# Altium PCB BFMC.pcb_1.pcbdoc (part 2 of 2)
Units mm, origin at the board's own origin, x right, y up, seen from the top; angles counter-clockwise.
Board outline 115.66 x 88.65 mm, 2 copper layers (Top Layer, Bottom Layer); 106 components, 51 nets, 277 pads, 103 vias.
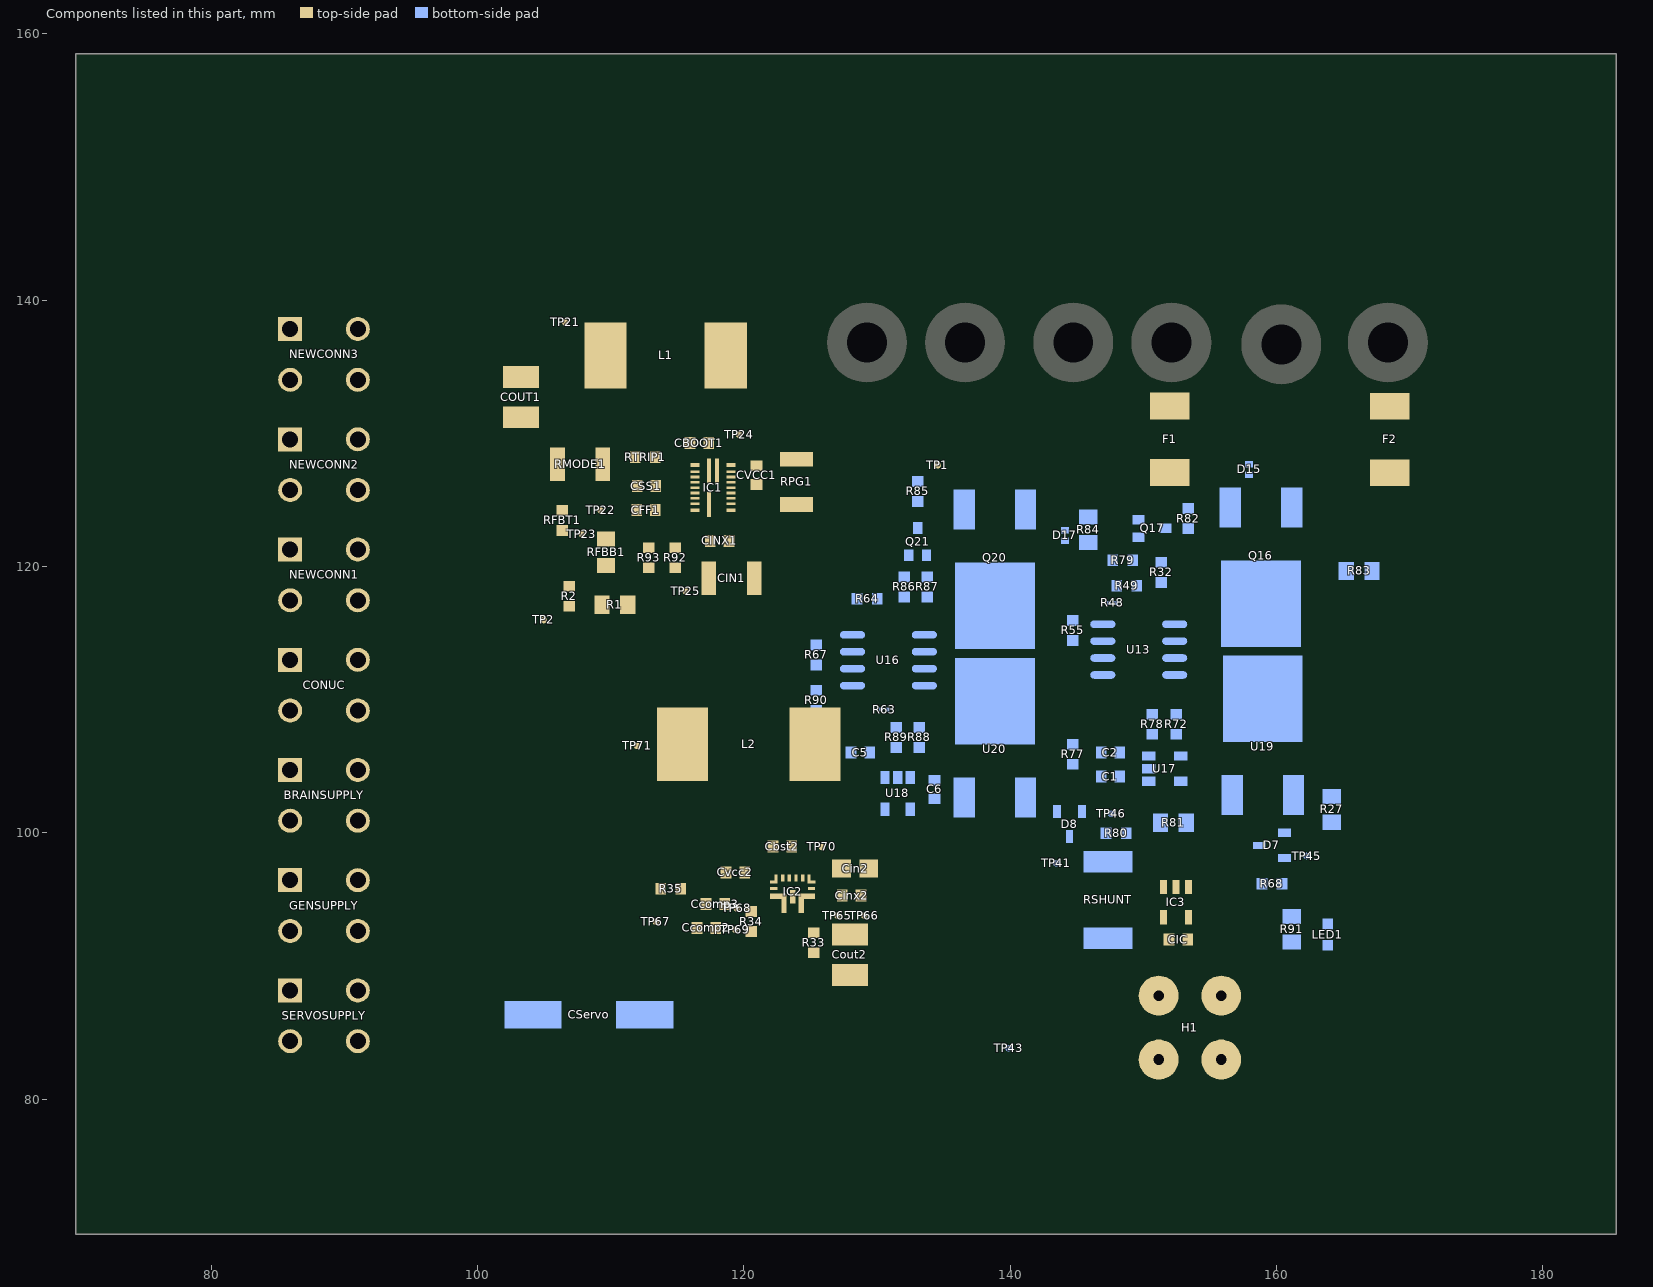
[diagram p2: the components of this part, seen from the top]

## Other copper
Top Layer:
  region net ISHUNT: 154.278,95.663 154.278,96.163 cw(c154.278,99.622) 153.676,96.216 153.676,95.61 cw(c154.278,92.204)
  region net UBATT: 150.494,96.19 150.494,95.69 cw(c150.494,90.33) 151.244,95.637 151.244,96.243 cw(c150.494,101.55)
  region net OUT_BATT: 150.494,93.91 150.494,93.41 cw(c150.494,92.265) 151.244,93.13 151.244,94.2 cw(c150.494,95.025)
  region net +5V: 153.16,92.38 153.66,92.38 ccw(c150.891,92.38) 153.556,93.13 153.263,93.13 ccw(c155.929,92.38)
  region net ADC1: 107.781,116.853 107.781,117.153 cw(c107.781,117.715) 107.331,117.378 107.331,116.628 cw(c107.781,116.29)
  region net ADC1: 106.017,117.153 106.017,116.853 cw(c106.017,116.29) 106.467,116.628 106.467,117.378 cw(c106.017,117.715)
  region net ADC1: 105.326,116.121 105.114,116.333 105.063,116.283 105.046,116.269 105.028,116.257 105.009,116.247 104.987,116.24 104.964,116.236 105.229,115.971 105.232,115.995 105.239,116.016 105.249,116.035 105.262,116.053 105.276,116.071
  region net VOUT1: 124.171,93.762 124.471,93.762 cw(c125.034,93.762) 124.521,93.994 124.121,93.994 cw(c123.607,93.762)
  region: 122.894,93.613 123.148,93.613 cw(c125.87,93.613) 123.174,93.994 122.867,93.994 cw(c120.171,93.613)
  region net VOUT1: 125.737,95.117 125.737,95.371 cw(c125.737,97.884) 125.371,95.398 125.371,95.09 cw(c125.737,92.604)
  region net SW_1: 123.821,95.944 123.521,95.944 cw(c122.517,95.944) 123.489,95.694 123.852,95.694 cw(c124.824,95.944)
  region: 123.17,95.825 122.916,95.825 cw(c122.44,95.825) 122.726,95.444 123.197,95.444 cw(c125.893,95.825)
  region: 121.874,95.371 121.874,95.117 cw(c121.874,94.93) 121.971,95.09 121.971,95.398 cw(c121.874,95.557)
  region net COMP: 119.611,93.991 119.823,94.203 119.792,94.236 119.778,94.253 119.765,94.27 119.753,94.289 119.744,94.308 119.738,94.329 119.735,94.35 119.47,94.085 119.493,94.082 119.513,94.075 119.531,94.066 119.548,94.054 119.563,94.04
  region net COMP: 119.348,94.679 119.136,94.466 119.188,94.417 119.202,94.4 119.215,94.383 119.225,94.364 119.232,94.343 119.236,94.319 119.501,94.584 119.478,94.588 119.457,94.594 119.437,94.604 119.418,94.616 119.399,94.63 119.365,94.662
  region net $3N2936: 119.023,93.01 119.023,92.71 119.047,92.704 119.07,92.69 119.094,92.669 119.116,92.643 119.18,92.564 119.198,92.545 119.198,92.92 119.179,92.911 119.159,92.915 119.138,92.928 119.095,92.969 119.072,92.989 119.048,93.004
  region net $3N2936: 119.704,92.44 119.704,92.74 119.691,92.742 119.679,92.746 119.667,92.753 119.655,92.762 119.643,92.773 119.632,92.785 119.61,92.813 119.558,92.887 119.548,92.9 119.539,92.911 119.529,92.92 119.529,92.545 119.549,92.555 119.569,92.549 119.589,92.533 119.631,92.486 119.653,92.464 119.678,92.447
  region net BOOT: 115.735,127.778 115.735,127.478 ccw(c115.735,128.028) 115.989,127.54 115.989,127.716 ccw(c115.735,127.227)
  region: 115.689,127.228 115.689,127.028 cw(c115.688,-126.865) 115.989,127.028 115.989,127.228 ccw(c115.688,-126.665)
  region net TRIP: 115.689,126.828 115.689,126.628 cw(c115.688,-127.265) 115.989,126.628 115.989,126.828 ccw(c115.688,-127.065)
  region net MODE: 115.689,126.428 115.689,126.228 cw(c115.688,-127.665) 115.989,126.228 115.989,126.428 ccw(c115.688,-127.465)
  region: 115.689,125.628 115.689,125.428 ccw(c115.689,126.535) 115.989,125.469 115.989,125.586 ccw(c115.689,124.52)
  region net EN: 115.689,124.828 115.689,124.628 cw(c115.688,-129.265) 115.989,124.628 115.989,124.828 ccw(c115.688,-129.065)
  region net PGOOD: 115.911,124.378 115.911,124.078 ccw(c115.911,124.158) 115.989,124.14 115.989,124.316 ccw(c115.911,124.298)
  region net VCC: 119.839,127.478 119.839,127.778 ccw(c119.839,126.117) 119.389,127.716 119.389,127.54 ccw(c119.839,129.139)
  region: 118.889,126.728 119.189,126.728 cw(c120.627,126.728) 119.22,127.028 118.857,127.028 cw(c117.45,126.728)
  region: 118.889,126.328 119.189,126.328 cw(c120.627,126.328) 119.22,126.628 118.857,126.628 cw(c117.45,126.328)
  region: 119.189,127.128 118.889,127.128 cw(c118.564,127.128) 118.689,126.828 119.389,126.828 cw(c119.514,127.128)
  region: 118.889,125.928 119.189,125.928 cw(c120.627,125.928) 119.22,126.228 118.857,126.228 cw(c117.45,125.928)
  region: 119.189,126.728 118.889,126.728 cw(c118.564,126.728) 118.689,126.428 119.389,126.428 cw(c119.514,126.728)
  region: 118.889,125.528 119.189,125.528 cw(c120.627,125.528) 119.22,125.828 118.857,125.828 cw(c117.45,125.528)
  region: 119.189,126.328 118.889,126.328 cw(c118.564,126.328) 118.689,126.028 119.389,126.028 cw(c119.514,126.328)
  region: 118.889,125.128 119.189,125.128 cw(c120.627,125.128) 119.22,125.428 118.857,125.428 cw(c117.45,125.128)
  region: 119.189,125.928 118.889,125.928 cw(c118.564,125.928) 118.689,125.628 119.389,125.628 cw(c119.514,125.928)
  region: 119.189,125.528 118.889,125.528 cw(c118.564,125.528) 118.689,125.228 119.389,125.228 cw(c119.514,125.528)
  region: 118.889,124.728 119.189,124.728 cw(c120.627,124.728) 119.22,125.028 118.857,125.028 cw(c117.45,124.728)
  region: 118.889,124.228 119.189,124.228 cw(c121.733,124.228) 119.22,124.628 118.857,124.628 cw(c116.344,124.228)
  region: 119.189,125.128 118.889,125.128 cw(c118.564,125.128) 118.689,124.828 119.389,124.828 cw(c119.514,125.128)
  region: 119.189,124.728 118.889,124.728 cw(c118.482,124.728) 118.689,124.378 119.389,124.378 cw(c119.595,124.728)
  region: 119.77,124.101 119.77,124.355 cw(c119.77,127.691) 119.389,124.377 119.389,124.079 cw(c119.77,120.765)
  region net SW: 118.116,128.509 117.862,128.509 cw(c114.526,128.509) 117.84,128.128 118.137,128.128 cw(c121.452,128.509)
  region net FB: 107.506,122.534 107.506,122.334 107.531,122.332 107.554,122.326 107.578,122.318 107.6,122.306 107.621,122.293 107.642,122.278 107.681,122.246 107.681,122.621 107.642,122.589 107.621,122.574 107.6,122.561 107.578,122.55 107.554,122.541 107.531,122.536
  region net FB: 108.187,122.334 108.187,122.534 108.162,122.536 108.139,122.541 108.116,122.55 108.093,122.561 108.072,122.574 108.051,122.589 108.012,122.621 108.012,122.246 108.051,122.278 108.072,122.293 108.093,122.306 108.116,122.318 108.139,122.326 108.162,122.332
  region net VBATT1: 149.758,84.733 149.405,84.379 149.495,84.284 149.559,84.21 149.609,84.146 149.654,84.08 149.686,84.026 149.715,83.971 149.734,83.929 149.75,83.886 149.763,83.843 149.774,83.8 149.779,83.771 149.783,83.742 149.785,83.712 149.785,83.683 149.784,83.653 149.781,83.623 149.777,83.593 149.77,83.563 149.762,83.532 149.751,83.502 150.635,84.386 150.605,84.376 150.575,84.367 150.544,84.361 150.514,84.356 150.484,84.353 150.455,84.352 150.425,84.353 150.396,84.355 150.366,84.358 150.323,84.367 150.28,84.378 150.237,84.392 150.195,84.409 150.153,84.429 150.098,84.459 150.044,84.492 149.979,84.538 149.902,84.599 149.817,84.676
  region net OUT_BATT2: 156.258,90.425 155.458,90.425 155.455,90.33 155.444,90.206 155.425,90.077 155.399,89.945 155.365,89.811 155.324,89.679 155.276,89.548 155.221,89.421 155.16,89.299 155.107,89.206 155.05,89.119 155.005,89.058 154.958,89 154.909,88.947 154.858,88.898 156.858,88.898 156.807,88.947 156.757,89 156.71,89.058 156.65,89.14 156.594,89.229 156.542,89.323 156.482,89.446 156.429,89.574 156.382,89.705 156.343,89.838 156.31,89.971 156.285,90.103 156.268,90.231 156.259,90.354
  region net EN: 114.051,121.545 114.051,121.291 cw(c114.051,120.815) 114.432,121.101 114.432,121.736 cw(c114.051,122.021)
  region net EN: 113.677,121.291 113.677,121.545 cw(c113.677,122.021) 113.296,121.736 113.296,121.101 cw(c113.677,120.815)
  region net VCCBOOST: 120.92,96.894 120.92,97.194 cw(c120.92,97.756) 120.47,97.419 120.47,96.669 cw(c120.92,96.331)
  region net VOUT1: 129.889,91.861 129.889,92.861 cw(c129.889,93.529) 129.321,93.179 129.321,91.544 cw(c129.889,91.193)
  region net FB_1: 124.089,91.24 124.089,90.74 cw(c124.089,85.381) 124.839,90.688 124.839,91.293 cw(c124.089,96.6)
  region net COMP: 119.717,94.247 119.717,93.947 cw(c119.717,93.44) 120.139,93.722 120.139,94.472 cw(c119.717,94.754)
  region net COMP: 120.742,94.881 120.488,94.881 cw(c120.011,94.881) 120.297,94.5 120.932,94.5 cw(c121.218,94.881)
  region net $3N2936: 119.689,92.74 119.689,92.44 cw(c119.689,91.878) 120.139,92.215 120.139,92.965 cw(c119.689,93.303)
  region net VCC: 120.064,127.778 120.064,127.478 cw(c120.064,126.915) 120.514,127.253 120.514,127.965 cw(c120.064,128.412)
  region net VCC: 121.907,127.315 121.907,127.815 cw(c121.907,130.148) 121.414,127.868 121.414,127.262 cw(c121.907,124.982)
  region net OUT_BATT: 112.31,116.98 112.31,117.28 cw(c112.31,117.842) 111.86,117.505 111.86,116.755 cw(c112.31,116.417)
  region net ADC1: 108.345,117.153 108.345,116.853 cw(c108.345,116.29) 108.795,116.628 108.795,117.378 cw(c108.345,117.715)
  region net ADC1: 92.249,112.75 92.249,113.25 92.205,113.252 92.165,113.256 92.139,113.26 92.115,113.265 92.092,113.271 92.07,113.279 92.049,113.287 92.028,113.296 92.009,113.306 91.981,113.323 91.954,113.341 91.929,113.361 91.896,113.391 91.847,113.439 91.711,113.586 91.652,113.645 91.619,113.675 91.619,112.325 91.682,112.385 91.807,112.518 91.879,112.594 91.912,112.625 91.937,112.646 91.963,112.666 91.99,112.684 92.019,112.7 92.038,112.709 92.059,112.718 92.081,112.726 92.103,112.733 92.127,112.738 92.152,112.743 92.191,112.748 92.234,112.75
  region net +5V: 153.66,93.18 153.16,93.18 cw(c151.771,93.18) 152.94,92.43 153.74,92.43 cw(c157.213,93.18)
  region net +5V: 153.17,90.78 153.67,90.78 cw(c157.721,90.78) 153.74,91.53 152.94,91.53 cw(c151.832,90.78)
  region net SW_1: 121.353,99.12 121.353,98.82 cw(c121.353,98.257) 121.803,98.595 121.803,99.345 cw(c121.353,99.682)
  region net SW_1: 122.141,98.139 122.395,98.139 cw(c122.871,98.139) 122.586,98.52 121.951,98.52 cw(c121.665,98.139)
  region net FB_1: 115.024,94.613 115.524,94.613 cw(c120.884,94.613) 115.577,95.363 114.972,95.363 cw(c109.665,94.613)
  region net FB_1: 116.128,95.694 116.128,95.994 cw(c116.128,96.556) 115.678,96.219 115.678,95.469 cw(c116.128,95.131)
  region net BOOT: 115.296,129.034 115.509,128.822 cw(c115.661,128.67) 115.82,128.815 115.564,129.715 cw(c114.65,129.68)
  region net FB: 114.062,124.129 114.062,124.329 cw(c114.062,124.704) 113.762,124.479 113.762,123.979 cw(c114.062,123.754)
  region net FB: 113.262,123.479 113.462,123.479 cw(c113.837,123.479) 113.612,123.779 113.112,123.779 cw(c112.887,123.479)
  region net SS_REFIN: 114.097,125.828 114.097,126.028 cw(c114.097,126.403) 113.797,126.178 113.797,125.678 cw(c114.097,125.453)
  region net FB: 107.096,122.334 107.096,122.534 cw(c107.096,122.909) 106.796,122.684 106.796,122.308 cw(c107.096,120.562)
  region net FB: 108.675,122.534 108.675,122.334 cw(c108.675,121.959) 108.975,122.184 108.975,122.555 cw(c108.675,124.678)
  region net FB: 110.652,121.965 110.652,122.165 cw(c110.652,122.54) 110.352,122.315 110.352,121.815 cw(c110.652,121.59)
  region net TRIP: 113.971,128.114 113.971,128.314 cw(c113.971,128.532) 113.763,128.464 113.763,127.964 cw(c113.971,127.895)
  region net $3N2936: 118.738,92.71 118.738,93.01 cw(c118.738,93.572) 118.288,93.235 118.288,92.485 cw(c118.738,92.147)
  region net MODE: 110.265,127.132 110.265,127.332 cw(c110.265,127.707) 109.965,127.482 109.965,126.982 cw(c110.265,126.757)
  region net PGOOD: 123.814,123.865 124.114,123.865 cw(c124.365,123.865) 124.339,124.115 123.589,124.115 cw(c123.562,123.865)
  region net VCC: 122.395,128.303 122.395,127.803 cw(c122.395,127.483) 122.714,127.515 122.714,128.615 cw(c122.395,128.622)
  region: 114.952,125.336 114.81,125.477 114.792,125.461 114.771,125.448 114.749,125.438 114.725,125.43 114.7,125.424 114.675,125.42 114.625,125.415 114.89,125.15 114.895,125.2 114.899,125.226 114.905,125.25 114.913,125.274 114.923,125.296 114.936,125.317
  region: 114.848,127.813 114.989,127.954 114.98,127.966 114.974,127.979 114.971,127.994 114.97,128.01 114.971,128.027 114.974,128.045 114.984,128.083 115.007,128.16 115.011,128.179 115.015,128.197 115.017,128.214 115.017,128.229 114.752,127.964 114.77,127.958 114.785,127.945 114.796,127.925 114.806,127.902 114.824,127.852 114.835,127.83
  region net PGOOD: 115.807,123.605 115.507,123.605 115.509,123.544 115.509,123.522 115.509,123.511 115.508,123.501 115.506,123.49 115.504,123.48 115.5,123.47 115.496,123.46 115.491,123.45 115.484,123.44 115.476,123.43 115.851,123.43 115.837,123.449 115.827,123.468 115.819,123.49 115.813,123.512 115.81,123.535 115.807,123.582
  region net PGOOD: 123.71,123.399 123.498,123.612 123.447,123.561 123.43,123.547 123.412,123.535 123.393,123.525 123.371,123.518 123.348,123.514 123.613,123.249 123.617,123.273 123.623,123.294 123.633,123.313 123.646,123.331 123.66,123.349
  region net COMP: 119.611,93.991 119.823,94.203 119.792,94.236 119.778,94.253 119.765,94.27 119.753,94.289 119.744,94.308 119.738,94.329 119.735,94.35 119.47,94.085 119.493,94.082 119.513,94.075 119.531,94.066 119.548,94.054 119.563,94.04
  region net COMP: 119.348,94.679 119.136,94.466 119.188,94.417 119.202,94.4 119.215,94.383 119.225,94.364 119.232,94.343 119.236,94.319 119.501,94.584 119.478,94.588 119.457,94.594 119.437,94.604 119.418,94.616 119.399,94.63 119.365,94.662
  region net ADC1: 107.781,116.853 107.781,117.153 cw(c107.781,117.715) 107.331,117.378 107.331,116.628 cw(c107.781,116.29)
  region net ADC1: 106.017,117.153 106.017,116.853 cw(c106.017,116.29) 106.467,116.628 106.467,117.378 cw(c106.017,117.715)
  region net VOUT1: 130.275,90.333 131.275,90.333 130.775,90.976 130.243,92.715
  region net SW_1: 124.048,96.999 123.794,96.999 ccw(c125.495,96.999) 123.816,96.726 124.026,96.726 ccw(c122.347,96.999)
Bottom Layer:
  region net $1N1798: 161.479,99.765 161.479,100.265 cw(c161.479,101.677) 161.089,100.32 161.089,99.71 cw(c161.479,98.352)
  region net $1N1798: 160.851,100.601 160.351,100.601 cw(c159.574,100.601) 160.298,100.32 160.904,100.32 cw(c161.628,100.601)
  region net UBATT: 157.489,99.315 157.489,98.815 ccw(c157.489,101.584) 158.239,98.918 158.239,99.211 ccw(c157.489,96.546)
  region net $1N1788: 143.814,102.366 143.214,102.366 ccw(c143.583,102.366) 143.338,102.09 143.689,102.09 ccw(c143.444,102.366)
  region net $1N1788: 143.314,100.806 143.714,100.806 cw(c144.219,100.806) 143.819,101.114 143.209,101.114 cw(c142.809,100.806)
  region net $1N2516: 149.398,121.549 149.898,121.549 cw(c150.809,121.549) 149.95,121.854 149.345,121.854 cw(c148.486,121.549)
  region net $1N2412: 152.88,122.615 152.88,123.115 cw(c152.88,128.474) 152.13,123.168 152.13,122.562 cw(c152.88,117.255)
  region net $1N20962: 150.464,118.315 150.464,118.815 cw(c150.464,121.641) 149.92,118.868 149.92,118.262 cw(c150.464,115.489)
  region net $1N20946: 147.755,117.683 148.055,117.683 cw(c148.618,117.683) 148.28,118.133 147.723,118.133 cw(c144.539,117.683)
  region net $1N2337: 157.01,127.14 157.01,126.64 cw(c157.01,-127.367) 157.653,126.639 157.653,126.64 157.653,127.14 157.653,127.139 ccw(c157.01,-126.867)
  region net $1N20674: 144.47,113.293 144.97,113.293 cw(c146.606,113.293) 145.152,114.043 144.288,114.043 cw(c142.834,113.293)
  region net $1N20674: 145.902,114.15 145.902,114.65 cw(c145.902,120.009) 145.152,114.703 145.152,114.097 cw(c145.902,108.79)
  region net $1N27792: 137.85,124.029 137.85,124.529 cw(c137.85,125.03) 137.364,124.904 137.364,123.654 cw(c137.85,123.527)
  region net $1N27792: 136.814,126.529 136.314,126.529 cw(c135.377,126.529) 135.939,125.779 137.189,125.779 cw(c137.752,126.529)
  region net $1N27799: 133.514,119.649 134.014,119.649 cw(c139.373,119.649) 134.066,120.399 133.461,120.399 cw(c128.154,119.649)
  region net $1N27793: 133.314,124.081 132.814,124.081 cw(c127.454,124.081) 132.761,123.331 133.366,123.331 cw(c138.673,124.081)
  region net $1N27811: 131.17,117.315 131.17,117.815 cw(c131.17,123.174) 130.42,117.868 130.42,117.262 cw(c131.17,111.955)
  region net $1N27807: 128.26,116.59 128.76,116.59 cw(c131.583,116.59) 128.813,117.133 128.207,117.133 cw(c125.437,116.59)
  region net $1N27822: 125.214,111.458 125.714,111.458 cw(c127.606,111.458) 125.869,112.208 125.005,112.208 cw(c123.763,111.458)
  region net $1N27822: 126.082,112.361 126.082,112.861 cw(c126.082,113.32) 125.869,112.914 125.869,112.309 cw(c126.082,111.902)
  region net VBATT1: 144.47,103.993 144.97,103.993 cw(c146.606,103.993) 145.152,104.743 144.288,104.743 cw(c142.834,103.993)
  region net $1N20674: 144.97,107.807 144.47,107.807 cw(c139.11,107.807) 144.417,107.057 145.023,107.057 cw(c150.33,107.807)
  region net +VCC2: 150.353,106.258 150.853,106.258 cw(c156.213,106.258) 150.906,107.008 150.3,107.008 cw(c144.993,106.258)
  region net +VCC2: 149.698,107.601 149.698,107.101 cw(c149.698,105.514) 150.232,107.008 150.232,107.815 cw(c149.698,108.374)
  region net $1N21052: 151.846,108.668 151.846,109.168 cw(c151.846,114.528) 151.096,109.221 151.096,108.615 cw(c151.846,103.308)
  region net $1N21052: 151.282,109.168 151.282,108.668 cw(c151.282,106.756) 152.032,108.515 152.032,109.321 cw(c151.282,111.08)
  region net $1N21052: 153.498,108.668 153.498,109.168 cw(c153.498,112.636) 152.896,109.221 152.896,108.615 cw(c153.498,105.2)
  region net $1N2516: 149.467,121.118 148.967,121.118 cw(c148.73,121.118) 148.814,120.897 149.62,120.897 cw(c149.703,121.118)
  region net $1N2516: 150.37,120.215 150.37,120.715 cw(c150.37,122.351) 149.62,120.897 149.62,120.033 cw(c150.37,118.578)
  region net UBATT: 158.66,94.983 159.16,94.983 cw(c161.072,94.983) 159.313,95.733 158.507,95.733 cw(c156.748,94.983)
  region net UBATT: 157.757,96.415 157.757,95.915 cw(c157.757,90.555) 158.507,95.862 158.507,96.468 cw(c157.757,101.774)
  region net $1N1798: 161.57,95.915 161.57,96.415 cw(c161.57,101.774) 160.82,96.468 160.82,95.862 cw(c161.57,90.555)
  region net $1N1788: 149.551,99.715 149.551,100.215 cw(c149.551,101.997) 149.12,100.268 149.12,99.662 cw(c149.551,97.932)
  region net $1N1788: 148.917,100.883 148.517,100.883 cw(c147.834,100.883) 148.314,100.397 149.12,100.397 cw(c149.6,100.883)
  region net $1N1798: 162.275,103.237 162.275,102.437 cw(c162.275,93.862) 163.475,102.353 163.475,103.072 ccw(c162.275,98.807)
  region net $1N1788: 150.351,101.015 150.351,100.515 cw(c150.351,100.134) 150.731,100.14 150.731,101.39 cw(c150.351,101.395)
  region net $1N2412: 152.199,123.115 152.199,122.615 cw(c152.199,120.824) 152.949,122.45 152.949,123.257 cw(c152.199,125.168)
  region net OUT_BATT1: 166.671,117.481 167.671,117.481 ccw(c162.133,117.481) 167.464,118.981 166.878,118.981 ccw(c172.208,117.481)
  region net OUT_BATT1: 167.63,121.558 166.83,121.558 cw(c158.254,121.558) 166.745,120.358 167.714,120.358 cw(c176.205,121.558)
  region net $1N2337: 165.547,120.834 165.047,120.834 cw(c164.555,120.834) 164.682,120.358 165.6,120.358 cw(c167.719,120.834)
  region net $1N27792: 144.425,122.125 144.425,121.625 cw(c144.425,120.687) 145.175,121.25 145.175,122.365 cw(c144.425,123.416)
  region net $1N27792: 133.311,127.044 132.811,127.044 cw(c132.55,127.044) 132.629,126.795 133.493,126.795 cw(c133.571,127.044)
  region net $1N27793: 132.814,123.732 133.314,123.732 cw(c134.974,123.732) 133.493,124.482 132.629,124.482 cw(c131.201,123.732)
  region net $1N27799: 132.582,119.468 132.582,118.968 cw(c132.582,113.608) 133.332,118.915 133.332,119.521 cw(c132.582,124.828)
  region net $1N27799: 134.014,120.371 133.514,120.371 cw(c131.877,120.371) 133.332,119.621 134.196,119.621 cw(c135.65,120.371)
  region net $1N32332: 132.654,107.133 132.413,106.949 cw(c131.618,106.154) 132.732,106.313 133.291,106.815 cw(c133.45,107.928)
  region net +VCC3: 133.414,108.978 132.914,108.978 cw(c131.639,108.978) 132.732,108.321 133.596,108.321 cw(c134.688,108.978)
  region net $1N32332: 132.166,107.197 132.214,107.573 cw(c134.817,110.177) 131.896,107.936 131.53,107.515 cw(c131.371,106.401)
  region net $1N27822: 125.714,111.871 125.214,111.871 cw(c119.854,111.871) 125.161,111.121 125.766,111.121 cw(c131.073,111.871)
  region net VBATT2: 125.064,107.608 125.864,107.608 ccw(c121.434,107.608) 125.698,108.808 125.229,108.808 ccw(c129.494,107.608)
  region net VBATT2: 126.346,109.061 126.346,109.361 cw(c126.346,109.924) 125.896,109.586 125.896,108.836 cw(c126.346,108.499)
  region net VBATT1: 149.58,105.07 149.58,104.57 cw(c149.58,103.448) 149.92,104.517 149.92,105.123 cw(c149.58,106.192)
  region net +VCC2: 150.853,106.87 150.353,106.87 cw(c149.415,106.87) 149.978,106.12 150.92,106.12 cw(c155.087,106.87)
  region net +VCC2: 149.41,106.02 149.41,105.52 cw(c149.41,103.028) 149.92,105.467 149.92,106.073 cw(c149.41,108.512)
  region net UBATT: 159.725,94.015 159.725,93.515 cw(c159.725,88.155) 160.475,93.462 160.475,94.068 cw(c159.725,99.374)
  region net $1N40141: 162.602,91.315 162.602,91.815 cw(c162.602,92.753) 161.852,92.19 161.852,91.263 cw(c162.602,85.956)
  region net $1N40141: 162.71,91.815 162.71,91.315 cw(c162.71,89.365) 163.46,91.165 163.46,91.965 cw(c162.71,93.765)
  region net $1N20931: 147.215,112.897 146.715,112.897 146.711,112.655 146.703,112.557 146.695,112.495 146.686,112.45 146.676,112.408 146.663,112.368 146.653,112.343 146.642,112.319 146.63,112.296 146.616,112.275 146.601,112.255 146.584,112.236 146.566,112.219 146.546,112.204 146.525,112.19 146.502,112.178 146.477,112.168 146.45,112.16 146.421,112.153 146.39,112.149 146.357,112.147 146.34,112.147 147.59,112.147 147.555,112.148 147.524,112.151 147.494,112.156 147.466,112.164 147.44,112.173 147.416,112.184 147.393,112.197 147.373,112.211 147.354,112.227 147.336,112.245 147.321,112.264 147.306,112.285 147.293,112.307 147.281,112.331 147.271,112.355 147.261,112.381 147.249,112.422 147.24,112.465 147.23,112.525 147.222,112.605 147.216,112.74
  region net $1N20931: 146.715,112.093 147.215,112.093 147.218,112.335 147.226,112.433 147.234,112.495 147.243,112.539 147.253,112.582 147.266,112.621 147.276,112.647 147.287,112.671 147.299,112.693 147.313,112.715 147.328,112.735 147.345,112.753 147.363,112.77 147.383,112.786 147.404,112.8 147.428,112.811 147.453,112.822 147.479,112.83 147.508,112.836 147.539,112.84 147.572,112.843 147.59,112.843 146.34,112.843 146.374,112.842 146.406,112.838 146.435,112.833 146.463,112.826 146.489,112.817 146.513,112.806 146.536,112.793 146.556,112.778 146.575,112.762 146.593,112.744 146.609,112.725 146.623,112.704 146.636,112.682 146.648,112.659 146.658,112.634 146.668,112.608 146.68,112.568 146.689,112.525 146.699,112.464 146.708,112.385 146.714,112.25
  region net $1N20931: 148.316,112.98 148.316,113.28 148.28,113.286 147.633,113.415 147.622,113.417 147.622,112.843 147.658,112.849 148.305,112.978
  region net $1N20674: 145.417,114.65 145.417,114.15 146.308,114.113 146.308,114.687
  region net +VCC2: 150.815,112.11 150.815,111.61 151.706,111.573 151.706,112.147
  region net $1N20962: 151.173,113.28 151.173,112.98 151.198,112.981 151.223,112.983 151.258,112.988 151.329,113.003 151.348,113.005 151.365,113.007 151.374,113.007 151.383,113.007 151.392,113.006 151.4,113.004 151.408,113.002 151.417,113 151.425,112.996 151.433,112.992 151.442,112.987 151.45,112.981 151.458,112.974 151.467,112.967 151.475,112.958 151.483,112.948 151.483,113.311 151.467,113.293 151.45,113.278 151.433,113.268 151.417,113.26 151.4,113.255 151.383,113.253 151.365,113.253 151.348,113.254 151.31,113.261 151.246,113.273 151.198,113.279
  region net $1N21052: 153.52,114.15 153.52,114.65 153.029,114.686 153.02,114.687 153.02,114.113 153.51,114.149
  region net $1N20946: 151.011,115.82 151.011,115.52 151.051,115.521 151.089,115.526 151.125,115.532 151.191,115.547 151.264,115.566 151.291,115.571 151.318,115.574 151.331,115.574 151.343,115.574 151.356,115.572 151.369,115.57 151.381,115.566 151.394,115.561 151.406,115.555 151.419,115.548 151.432,115.539 151.444,115.529 151.457,115.517 151.47,115.503 151.483,115.488 151.483,115.851 151.47,115.836 151.457,115.823 151.444,115.811 151.432,115.8 151.419,115.792 151.406,115.784 151.394,115.778 151.381,115.774 151.369,115.77 151.356,115.767 151.343,115.766 151.331,115.765 151.318,115.766 151.291,115.768 151.264,115.774 151.175,115.796 151.125,115.808 151.089,115.814 151.051,115.818
  region net $1N27802: 128.415,112.097 127.915,112.097 127.911,111.855 127.903,111.757 127.895,111.695 127.886,111.65 127.876,111.608 127.863,111.568 127.853,111.543 127.842,111.519 127.83,111.496 127.816,111.475 127.801,111.455 127.784,111.436 127.766,111.419 127.746,111.404 127.725,111.39 127.702,111.378 127.677,111.368 127.65,111.36 127.621,111.353 127.59,111.349 127.557,111.347 127.54,111.347 128.79,111.347 128.755,111.348 128.724,111.351 128.694,111.356 128.666,111.364 128.64,111.373 128.616,111.384 128.593,111.397 128.573,111.411 128.554,111.427 128.536,111.445 128.521,111.464 128.506,111.485 128.493,111.507 128.481,111.531 128.471,111.555 128.461,111.581 128.449,111.622 128.44,111.665 128.43,111.725 128.422,111.805 128.416,111.94
  region net $1N27802: 128.92,110.455 129.297,110.502 129.275,110.525 129.254,110.551 129.233,110.579 129.203,110.624 129.177,110.672 129.153,110.722 129.133,110.774 129.122,110.809 129.113,110.844 129.106,110.879 129.102,110.914 129.1,110.948 129.101,110.981 129.105,111.012 128.284,110.773 128.326,110.771 128.369,110.766 128.412,110.757 128.456,110.745 128.499,110.731 128.542,110.714 128.606,110.684 128.668,110.65 128.728,110.612 128.785,110.571 128.839,110.529 128.889,110.484
  region net $1N27802: 127.915,111.293 128.415,111.293 128.418,111.535 128.426,111.633 128.434,111.695 128.443,111.739 128.453,111.782 128.466,111.821 128.476,111.847 128.487,111.871 128.499,111.893 128.513,111.915 128.528,111.935 128.545,111.953 128.563,111.97 128.583,111.986 128.604,112 128.628,112.011 128.653,112.022 128.679,112.03 128.708,112.036 128.739,112.04 128.772,112.043 128.79,112.043 127.54,112.043 127.574,112.042 127.606,112.038 127.635,112.033 127.663,112.026 127.689,112.017 127.713,112.006 127.736,111.993 127.756,111.978 127.775,111.962 127.793,111.944 127.809,111.925 127.823,111.904 127.836,111.882 127.848,111.859 127.858,111.834 127.868,111.808 127.88,111.768 127.889,111.725 127.899,111.664 127.908,111.585 127.914,111.45
  region net $1N27822: 127.071,113.85 127.071,113.35 127.483,113.314 127.508,113.313 127.508,113.887 127.096,113.851
  region net +VCC3: 134.712,110.784 134.712,111.284 134.641,111.286 134.531,111.296 134.417,111.311 134.34,111.326 134.296,111.336 134.449,110.887 134.459,110.897 134.471,110.902 134.485,110.903 134.5,110.9 134.515,110.893 134.532,110.884 134.567,110.861 134.623,110.821 134.642,110.809 134.66,110.799 134.678,110.791 134.695,110.786
  region net $1N27811: 134.738,112.08 134.738,112.58 134.721,112.578 134.704,112.572 134.685,112.564 134.666,112.554 134.587,112.501 134.549,112.478 134.531,112.469 134.515,112.462 134.5,112.459 134.487,112.46 134.475,112.466 134.466,112.476 134.466,112.183 134.475,112.194 134.487,112.199 134.5,112.2 134.515,112.197 134.531,112.191 134.549,112.182 134.587,112.158 134.666,112.106 134.685,112.095 134.704,112.087 134.721,112.082
  region net $1N32332: 132.015,113.85 132.015,113.35 132.906,113.313 132.906,113.887
  region net $1N27807: 132.015,115.12 132.015,114.62 132.032,114.621 132.05,114.623 132.089,114.63 132.132,114.642 132.248,114.683 132.416,114.744 132.462,114.757 132.505,114.766 132.525,114.769 132.545,114.771 132.563,114.771 132.581,114.77 132.597,114.767 132.612,114.762 132.626,114.756 132.639,114.747 132.649,114.736 132.659,114.723 132.659,115.016 132.649,115.003 132.639,114.992 132.626,114.984 132.612,114.977 132.597,114.972 132.581,114.969 132.563,114.968 132.545,114.968 132.525,114.97 132.484,114.977 132.439,114.988 132.369,115.011 132.177,115.082 132.11,115.104 132.069,115.114 132.05,115.117 132.032,115.119
  region net OUT_BATT1: 158.772,82.48 158.772,83.48 158.659,83.483 158.544,83.493 158.41,83.511 158.256,83.54 158.084,83.583 157.894,83.64 157.67,83.721 157.433,83.82 157.187,83.938 156.94,84.073 156.727,84.203 156.687,84.23 156.687,81.73 156.896,81.861 157.14,81.997 157.383,82.117 157.618,82.218 157.842,82.302 158.05,82.367 158.222,82.411 158.376,82.443 158.511,82.463 158.626,82.474 158.74,82.479
  region net VBATT2: 148.512,88.18 148.512,87.38 148.607,87.377 148.732,87.366 148.861,87.348 148.993,87.321 149.126,87.287 149.259,87.246 149.39,87.198 149.517,87.144 149.639,87.083 149.731,87.029 149.818,86.972 149.88,86.927 149.937,86.88 149.991,86.831 150.039,86.78 150.039,88.78 149.991,88.729 149.937,88.68 149.88,88.632 149.797,88.573 149.708,88.517 149.615,88.464 149.492,88.404 149.364,88.351 149.232,88.305 149.099,88.265 148.966,88.232 148.834,88.208 148.706,88.19 148.583,88.181
  region net $1N20946: 148.507,117.115 148.507,117.415 cw(c148.507,125.857) 148.057,117.427 148.057,117.103 cw(c148.507,108.672)
  region net $1N20946: 148.055,117.877 147.755,117.877 cw(c82.94,117.877) 147.754,117.427 148.057,117.427 cw(c212.87,117.877)
  region net $1N20931: 147.272,116.865 147.572,116.865 ccw(c147.087,116.865) 147.51,117.103 147.334,117.103 ccw(c147.757,116.865)
  region net $1N27807: 130.955,109.877 130.655,109.877 cw(c65.84,109.877) 130.654,109.427 130.957,109.427 cw(c195.77,109.877)
  region net $1N27802: 130.054,109.745 129.852,109.522 cw(c128.485,108.155) 130.17,109.103 130.17,109.427 ccw(c129.769,109.46)
  region net $1N2516: 150.182,120.715 150.182,120.215 cw(c150.182,114.855) 150.932,120.162 150.932,120.611 ccw(c150.182,117.946)
  region net $1N20962: 152.246,118.661 152.246,118.961 cw(c152.246,119.524) 151.796,119.186 151.796,118.436 cw(c152.246,118.099)
  region net $1N20962: 150.71,119.061 150.71,118.561 cw(c150.71,118.325) 150.932,118.408 150.932,119.215 cw(c150.71,119.298)
  region net $1N27811: 131.662,116.881 132.162,116.881 cw(c132.602,116.881) 132.496,117.308 131.632,117.308 cw(c128.641,116.881)
  region net $1N27811: 130.882,117.815 130.882,117.315 cw(c130.882,74.707) 131.632,117.308 131.632,118.115 cw(c130.882,118.903)
  region net $1N27799: 133.246,118.968 133.246,119.468 cw(c133.246,121.38) 132.496,119.621 132.496,118.815 cw(c133.246,117.056)
  region net $1N1798: 163.278,102.437 163.278,103.237 cw(c163.278,104.737) 162.078,103.837 162.078,101.837 cw(c163.278,100.937)
  region net $1N1788: 142.863,102.48 142.863,103.08 cw(c142.863,104.205) 141.963,103.53 141.963,102.03 cw(c142.863,101.355)
  region net $1N2337: 158.021,124.029 158.021,124.529 cw(c158.021,125.331) 157.342,124.904 157.342,123.654 cw(c158.021,123.227)
  region net $1N2337: 154.992,124.529 154.992,124.029 cw(c154.992,123.091) 155.742,123.654 155.742,124.904 cw(c154.992,125.466)
  region net $1N2337: 156.814,126.444 156.314,126.444 cw(c155.77,126.444) 155.939,125.927 157.189,125.927 cw(c157.359,126.444)
  region net ISHUNT: 92.249,108.94 92.249,109.44 92.205,109.442 92.165,109.446 92.139,109.45 92.115,109.455 92.092,109.461 92.07,109.469 92.049,109.477 92.028,109.486 92.009,109.496 91.981,109.513 91.954,109.531 91.929,109.551 91.896,109.581 91.847,109.629 91.711,109.776 91.652,109.835 91.619,109.865 91.619,108.515 91.682,108.575 91.807,108.708 91.879,108.784 91.912,108.815 91.937,108.836 91.963,108.856 91.99,108.874 92.019,108.89 92.038,108.899 92.059,108.908 92.081,108.916 92.103,108.923 92.127,108.928 92.152,108.933 92.191,108.938 92.234,108.94
  region net UBATT: 147.114,96.604 147.614,96.604 cw(c148.055,96.604) 147.989,97.04 146.739,97.04 cw(c146.673,96.604)
  region net VBATT1: 147.99,103.02 148.49,103.02 cw(c150.44,103.02) 148.64,103.77 147.84,103.77 cw(c146.04,103.02)
  region net VBATT1: 148.98,103.97 148.98,104.47 cw(c148.98,104.859) 148.64,104.67 148.64,103.77 cw(c148.98,103.581)
  region net +VCC2: 149.16,105.77 149.16,106.27 cw(c149.16,107.046) 148.64,106.47 148.64,105.57 cw(c149.16,104.994)
  region net PGOOD: 116.004,123.115 116.004,123.415 115.933,123.415 115.91,123.417 115.889,123.421 115.868,123.428 115.848,123.438 115.829,123.452 115.829,123.077 115.848,123.091 115.868,123.102 115.889,123.108 115.91,123.112 115.933,123.114
  region net PGOOD: 123.023,123.415 123.023,123.115 123.095,123.114 123.117,123.112 123.138,123.108 123.159,123.102 123.179,123.091 123.198,123.077 123.198,123.452 123.179,123.438 123.159,123.428 123.138,123.421 123.117,123.417 123.095,123.415
  region net ISHUNT: 140.11,83.31 140.464,83.664 ccw(c139.95,83.15) 140.183,83.838 139.936,83.591 ccw(c140.624,83.824)
  region net $1N1798: 161.454,102.661 161.101,103.014 cw(c160.128,103.986) 160.878,102.833 161.274,102.437 cw(c162.427,101.688)
  region net $1N27807: 130.955,114.135 130.956,114.166 130.959,114.197 130.964,114.226 130.97,114.254 130.979,114.281 130.989,114.307 131.001,114.331 131.014,114.355 131.029,114.377 131.045,114.399 131.063,114.419 131.082,114.439 131.102,114.457 131.123,114.474 131.146,114.49 131.181,114.513 131.219,114.533 131.259,114.551 131.301,114.567 131.344,114.581 131.389,114.592 131.45,114.604 131.512,114.613 131.576,114.618 131.64,114.62 131.64,115.12 131.577,115.122 131.511,115.128 131.424,115.142 131.333,115.161 131.222,115.191 131.11,115.228 131,115.272 130.894,115.321 130.81,115.365 130.732,115.413 130.675,115.453 130.636,115.483 130.599,115.515 130.577,115.536 130.224,115.183 130.254,115.15 130.285,115.114 130.325,115.06 130.374,114.986 130.42,114.905 130.473,114.801 130.521,114.692 130.563,114.581 130.599,114.47 130.623,114.38 130.64,114.293 130.65,114.227 130.654,114.179 130.655,114.135
  region net $1N2337: 158.021,124.029 158.021,124.529 cw(c158.021,125.331) 157.342,124.904 157.342,123.654 cw(c158.021,123.227)
  region net $1N2337: 154.992,124.529 154.992,124.029 cw(c154.992,123.091) 155.742,123.654 155.742,124.904 cw(c154.992,125.466)

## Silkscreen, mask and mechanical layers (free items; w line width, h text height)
Top Silkscreen Layer:
  text "BFMC POWER BOARD A SAMPLE (FOOTPRINT>0603)" at 93.6,149.1 h3.05
  text "Engine" at 123.72,129.42 h3.05
  text "Bat1" at 157.508,129.051 h3.05
  text "Bat2" at 141.48,128.82 h3.05
  text "BFMC POWER BOARD  V1.1" at 105.601,83.16 h3.05
Mechanical Layer:
  circle w0.025: c97.259,134.048 r1.25
  circle w0.025: c97.276,111.161 r1.25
